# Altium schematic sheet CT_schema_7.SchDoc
size 250 x 169 mm
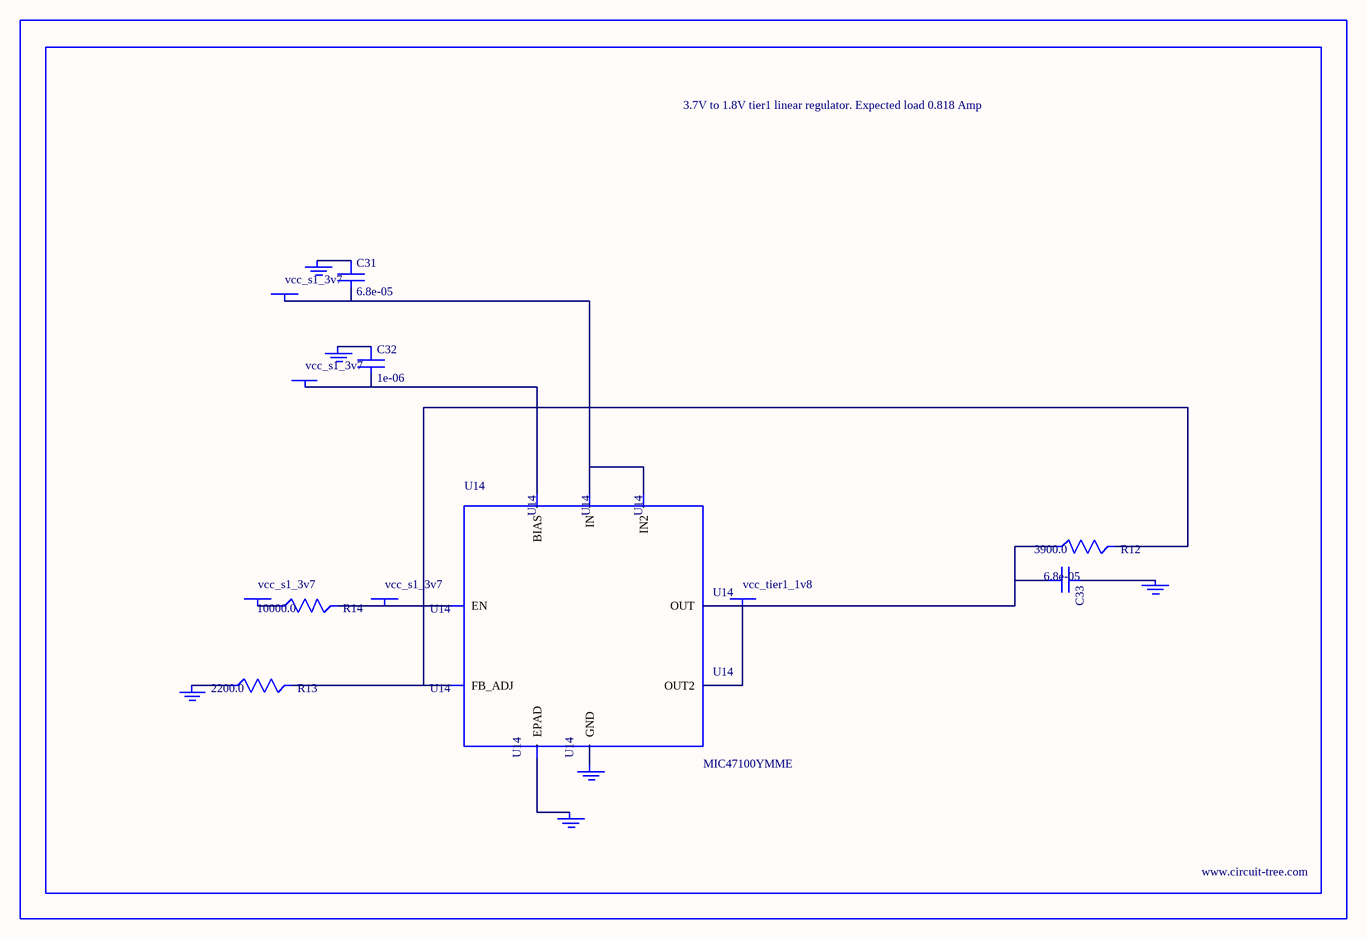
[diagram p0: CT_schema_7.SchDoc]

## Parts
BORDER6  (no value)
C31  6.8e-05  [2220]
C32  1e-06  [C0603]
C33  6.8e-05  [2220]
GND_INSTANCE_6_0  (no value)
GND_INSTANCE_6_1  (no value)
GND_INSTANCE_6_2  (no value)
GND_INSTANCE_6_3  (no value)
GND_INSTANCE_6_4  (no value)
GND_INSTANCE_6_5  (no value)
POWER_INSTANCE_6_0  vcc_s1_3v7
POWER_INSTANCE_6_1  vcc_s1_3v7
POWER_INSTANCE_6_2  vcc_s1_3v7
POWER_INSTANCE_6_3  vcc_s1_3v7
POWER_INSTANCE_6_4  vcc_tier1_1v8
R12  3900.0  [R0603]
R13  2200.0  [R0603]
R14  10000.0  [R0603]
U14  MIC47100YMME  [MSOP-8_EP]

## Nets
NetC31_1: C31.1 GND_INSTANCE_6_0.0(GND)
NetC31_2: C31.2 POWER_INSTANCE_6_0.0(PWR) U14.1(IN) U14.2(IN2)
NetC32_1: C32.1 GND_INSTANCE_6_1.0(GND)
NetC32_2: C32.2 POWER_INSTANCE_6_1.0(PWR) U14.4(BIAS)
NetC33_1: C33.1 GND_INSTANCE_6_3.0(GND)
NetC33_2: C33.2 POWER_INSTANCE_6_4.0(PWR) R12.1 U14.7(OUT) U14.8(OUT2)
NetGND_INSTANCE_6_2_0: GND_INSTANCE_6_2.0(GND) R13.1
NetGND_INSTANCE_6_4_0: GND_INSTANCE_6_4.0(GND) U14.EPAD
NetGND_INSTANCE_6_5_0: GND_INSTANCE_6_5.0(GND) U14.3(GND)
NetPOWER_INSTANCE_6_2_0: POWER_INSTANCE_6_2.0(PWR) R14.1
NetPOWER_INSTANCE_6_3_0: POWER_INSTANCE_6_3.0(PWR) R14.2 U14.5(EN)
NetR12_2: R12.2 R13.2 U14.6(FB_ADJ)

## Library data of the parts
BORDER6 = BORDER_PAGE6
C31 C33 = C5750X5R1A686M
C32 = C0603C105K3RACTU
GND_INSTANCE_6_0-GND_INSTANCE_6_5 = GND
POWER_INSTANCE_6_0-POWER_INSTANCE_6_4 = PWR
R12 = RC0603JR-073K9L
R13 = RC0603JR-072K2L
R14 = RC0603JR-0710KL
